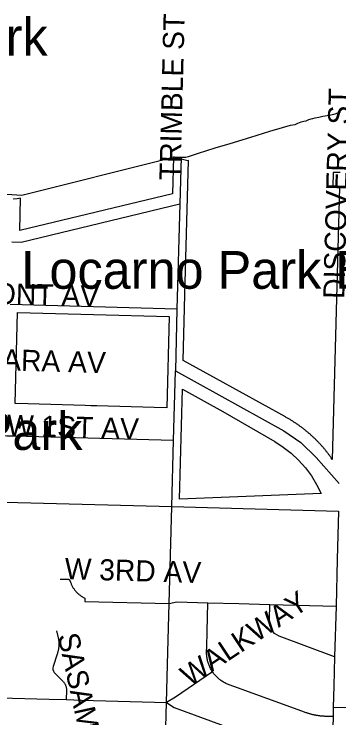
# Model space of a CAD drawing. Extents: x 482780 to 486928, y 5455974 to 5459836.
# Drawn here: x 484821 to 485252, y 5457356 to 5458288 of the extents above; entities that cross this region are included whole.
import ezdxf

# ---------------------------------------------------------------- set-up
doc = ezdxf.new("R2010")
doc.units = 0
for name, color, linetype in [('ParkLabels', 7, 'Continuous'), ('Parks', 7, 'Continuous'), ('StreetNames', 7, 'Continuous'), ('Streets', 7, 'Continuous')]:
    doc.layers.add(name, color=color, linetype=linetype)

msp = doc.modelspace()

# ---------------------------------------------------------------- linework, layer by layer
at = {"layer": 'Parks'}
for points in [[(484724.68, 5458054.79), (484831.03, 5458048.04), (485025.24, 5458096.46), (485029.94, 5458098.11), (485032.12, 5458098.56), (485033.54, 5458098.56), (485037.02, 5458098.36), (485048.62, 5458098.48), (485052.26, 5458098.98), (485057.52, 5458100.79), (485065.32, 5458103.77), (485087.63, 5458110.5), (485107.43, 5458116.47), (485134.69, 5458124.81), (485160.03, 5458132.57), (485176.84, 5458137.55), (485187.53, 5458140.47), (485190.31, 5458140.99), (485193.53, 5458141.57), (485197.17, 5458143.12), (485201.43, 5458145.07), (485204.99, 5458145.73), (485208.33, 5458146.37), (485211.87, 5458148.02), (485214.63, 5458149.17), (485217.22, 5458149.65), (485220.03, 5458150.17), (485225.09, 5458151.4), (485230.33, 5458152.67), (485233.27, 5458153.18), (485240.93, 5458154.27), (485246.55, 5458155.64), (485253.69, 5458158.37)], [(485253.08, 5458077.77), (485244.18, 5458078.02), (485243.68, 5458058.87), (485252.57, 5458058.62), (485242.83, 5457698.06), (485241.38, 5457700.11), (485240.79, 5457700.94), (485240.2, 5457701.76), (485239.61, 5457702.58), (485239.01, 5457703.39), (485238.4, 5457704.2), (485237.79, 5457705.01), (485237.18, 5457705.81), (485236.56, 5457706.62), (485235.94, 5457707.41), (485235.31, 5457708.21), (485234.68, 5457709), (485234.04, 5457709.79), (485233.4, 5457710.57), (485232.76, 5457711.35), (485232.11, 5457712.13), (485231.45, 5457712.9), (485230.79, 5457713.67), (485230.13, 5457714.43), (485229.46, 5457715.19), (485228.79, 5457715.95), (485228.12, 5457716.7), (485227.44, 5457717.45), (485226.75, 5457718.2), (485226.07, 5457718.94), (485225.37, 5457719.68), (485224.68, 5457720.42), (485223.98, 5457721.15), (485223.27, 5457721.87), (485222.56, 5457722.6), (485221.85, 5457723.31), (485221.13, 5457724.03), (485220.41, 5457724.74), (485219.69, 5457725.45), (485218.96, 5457726.15), (485218.23, 5457726.85), (485217.49, 5457727.54), (485216.75, 5457728.23), (485216, 5457728.92), (485215.26, 5457729.6), (485214.5, 5457730.28), (485213.75, 5457730.95), (485212.99, 5457731.62), (485212.23, 5457732.28), (485211.46, 5457732.94), (485210.69, 5457733.6), (485209.91, 5457734.25), (485209.13, 5457734.9), (485208.35, 5457735.54), (485207.57, 5457736.18), (485206.78, 5457736.81), (485205.99, 5457737.44), (485205.19, 5457738.07), (485204.39, 5457738.69), (485203.59, 5457739.3), (485202.78, 5457739.91), (485201.97, 5457740.52), (485201.16, 5457741.12), (485200.34, 5457741.72), (485199.52, 5457742.31), (485198.7, 5457742.9), (485197.87, 5457743.49), (485197.04, 5457744.07), (485196.21, 5457744.64), (485195.37, 5457745.21), (485194.53, 5457745.78), (485193.69, 5457746.34), (485192.84, 5457746.89), (485191.99, 5457747.44), (485191.14, 5457747.99), (485190.28, 5457748.53), (485189.42, 5457749.07), (485188.56, 5457749.6), (485187.7, 5457750.12), (485186.83, 5457750.65), (485185.96, 5457751.16), (485185.09, 5457751.67), (485184.21, 5457752.18), (485183.33, 5457752.68), (485182.45, 5457753.18), (485181.57, 5457753.67), (485180.68, 5457754.16), (485089.12, 5457804.57), (485045.17, 5457828.76), (485047.46, 5457915.91), (485052.13, 5458093.66), (485051.32, 5458093.59), (485032.11, 5458098.17), (485030.82, 5458049.81), (484828.42, 5458001.06), (484829.52, 5458043.76), (484824.88, 5458043.24), (484819.72, 5458042.76)]]:
    msp.add_lwpolyline(points, dxfattribs=at)
for points in [[(484825.52, 5457892.61), (484926.02, 5457889.93), (485026.52, 5457887.26), (485023.32, 5457766.41), (485006.62, 5457766.86), (484991.42, 5457767.27), (484976.17, 5457767.68), (484960.92, 5457768.1), (484945.72, 5457768.51), (484930.47, 5457768.92), (484922.82, 5457769.13), (484915.22, 5457769.34), (484899.97, 5457769.75), (484884.77, 5457770.16), (484869.52, 5457770.58), (484854.27, 5457770.99), (484839.02, 5457771.4), (484822.28, 5457771.85)], [(485166.63, 5457721.51), (485177.89, 5457714.27), (485188.44, 5457706.04), (485198.21, 5457696.88), (485207.11, 5457686.88), (485215.06, 5457676.11), (485222, 5457664.66), (485227.87, 5457652.63), (485040.27, 5457645.26), (485044.12, 5457791.06), (485097.88, 5457761.46)]]:
    msp.add_lwpolyline(points, close=True, dxfattribs=at)
at = {"layer": 'Streets'}
for points in [[(485042.26, 5458098.43), (485040.65, 5458036.5)], [(484818.03, 5457986.12), (484830.14, 5457985.8), (485040.65, 5458036.5), (485036.92, 5457897.06), (485034.78, 5457815.39), (485178.43, 5457735.86), (485200.98, 5457720.3), (485221.37, 5457700.44), (485252.11, 5457665.92)], [(485036.92, 5457897.06), (484815.82, 5457902.94)], [(485021.83, 5457326.75), (485023.18, 5457376.21), (485024.92, 5457442.66), (485026.61, 5457507.02), (485028.32, 5457571.26), (485030.02, 5457635.55), (485032.31, 5457722.91), (485034.78, 5457815.39)], [(485032.31, 5457722.91), (484821.19, 5457728.63), (484811.18, 5457728.59), (484590.21, 5457735.74)], [(483813.72, 5457599.7), (483930.19, 5457625.05), (483953.6, 5457629.93), (483977.08, 5457634.4), (484000.64, 5457638.46), (484024.27, 5457642.11), (484047.96, 5457645.35), (484071.7, 5457648.17), (484095.48, 5457650.57), (484119.3, 5457652.56), (484143.16, 5457654.14), (484167.04, 5457655.3), (484190.93, 5457656.04), (484214.84, 5457656.37), (484238.75, 5457656.27), (484262.65, 5457655.76), (484264.42, 5457655.71), (484364.4, 5457653.1), (484476.08, 5457650.28), (484587.88, 5457647.46), (484661.8, 5457645.45), (484808.97, 5457641.49), (485030.02, 5457635.55), (485251.12, 5457629.52)], [(485251.12, 5457629.52), (485249.39, 5457565.24), (485247.73, 5457503.43), (485245.91, 5457436.28), (485244.69, 5457397.85), (485244.13, 5457370.04), (485243.81, 5457357.35), (485242.35, 5457298)], [(484882.09, 5457539.54), (484893.45, 5457539.21), (484893.58, 5457539.07), (484893.7, 5457538.92), (484893.83, 5457538.78), (484893.95, 5457538.63), (484894.07, 5457538.48), (484894.18, 5457538.33), (484894.3, 5457538.17), (484894.41, 5457538.02), (484894.52, 5457537.86), (484894.62, 5457537.7), (484894.73, 5457537.53), (484894.83, 5457537.37), (484894.92, 5457537.2), (484895.02, 5457537.04), (484895.11, 5457536.87), (484895.2, 5457536.7), (484895.28, 5457536.53), (484895.36, 5457536.35), (484895.44, 5457536.18), (484895.52, 5457536), (484895.59, 5457535.82), (484895.66, 5457535.64), (484895.73, 5457535.46), (484895.78, 5457535.31), (484896.12, 5457534.37), (484896.46, 5457533.49), (484896.82, 5457532.62), (484897.2, 5457531.76), (484897.61, 5457530.92), (484898.04, 5457530.09), (484898.49, 5457529.26), (484898.95, 5457528.45), (484899.45, 5457527.65), (484899.96, 5457526.86), (484900.5, 5457526.09), (484901.05, 5457525.33), (484901.62, 5457524.59), (484902.21, 5457523.86), (484902.82, 5457523.16), (484903.45, 5457522.45), (484904.11, 5457521.78), (484904.77, 5457521.11), (484905.45, 5457520.47), (484906.15, 5457519.84), (484906.85, 5457519.25), (484907.59, 5457518.66), (484908.35, 5457518.08), (484909.11, 5457517.53), (484909.87, 5457517), (484910.67, 5457516.49), (484911.46, 5457516.01), (484912.27, 5457515.55), (484913.11, 5457515.1), (484913.95, 5457514.67), (484914.69, 5457514.32), (484914.62, 5457509.8), (485026.61, 5457507.02), (485036.75, 5457509.15), (485077.83, 5457508.05), (485118.96, 5457506.91), (485160.09, 5457505.83), (485247.73, 5457503.43)], [(485243.81, 5457357.35), (485233.77, 5457357.63), (485232.82, 5457357.66), (485231.91, 5457357.7), (485230.96, 5457357.76), (485230.01, 5457357.82), (485229.06, 5457357.9), (485228.11, 5457357.98), (485227.21, 5457358.07), (485226.3, 5457358.18), (485225.34, 5457358.3), (485224.4, 5457358.43), (485223.48, 5457358.57), (485222.55, 5457358.71), (485221.24, 5457358.94), (485220.7, 5457359.04), (485219.8, 5457359.22), (485218.89, 5457359.41), (485218.74, 5457359.45), (485217.93, 5457359.62), (485217.05, 5457359.82), (485216.12, 5457360.06), (485215.2, 5457360.29), (485214.33, 5457360.53), (485213.41, 5457360.78), (485212.52, 5457361.05), (485211.6, 5457361.33), (485210.7, 5457361.62), (485209.81, 5457361.91), (485208.94, 5457362.21), (485208.04, 5457362.53), (485202.6, 5457364.5), (485112.11, 5457397.26), (485106.14, 5457399.43), (485105.02, 5457399.85), (485103.88, 5457400.33), (485102.77, 5457400.82), (485101.65, 5457401.34), (485100.52, 5457401.92), (485099.45, 5457402.5), (485098.36, 5457403.13), (485097.31, 5457403.78), (485096.28, 5457404.46), (485095.26, 5457405.17), (485094.26, 5457405.9), (485093.28, 5457406.66), (485092.35, 5457407.44), (485092.07, 5457407.67), (485091.4, 5457408.25), (485090.47, 5457409.1), (485089.58, 5457409.97), (485088.75, 5457410.82), (485087.9, 5457411.72), (485087.05, 5457412.7), (485086.27, 5457413.64), (485085.5, 5457414.62), (485084.76, 5457415.62), (485084.07, 5457416.61), (485084.07, 5457416.61), (485083.38, 5457417.64), (485082.72, 5457418.71), (485082.1, 5457419.77), (485081.5, 5457420.85), (485080.93, 5457421.97), (485080.41, 5457423.04), (485079.88, 5457424.2), (485079.4, 5457425.37), (485078.97, 5457426.5), (485078.68, 5457427.28), (485078.55, 5457427.64), (485078.16, 5457428.84), (485077.8, 5457430.06), (485077.5, 5457431.24), (485077.21, 5457432.43), (485076.96, 5457433.64), (485076.73, 5457434.86), (485076.55, 5457436.11), (485076.4, 5457437.32), (485076.28, 5457438.56), (485076.19, 5457439.78), (485076.13, 5457441.04), (485076.12, 5457442.29), (485076.13, 5457443.46), (485076.3, 5457449.87), (485076.83, 5457469.97), (485077.83, 5457508.05)], [(485245.91, 5457436.28), (485172.16, 5457463.98), (485166.28, 5457467.31), (485162.44, 5457471.91), (485160.13, 5457477.8), (485159.62, 5457485.98), (485160.09, 5457505.83)], [(484877.24, 5457470.94), (484879.49, 5457461.53), (484879.67, 5457460.52), (484879.82, 5457459.57), (484879.95, 5457458.66), (484880.05, 5457457.71), (484880.14, 5457456.75), (484880.2, 5457455.81), (484880.25, 5457454.88), (484880.26, 5457453.94), (484880.26, 5457452.98), (484880.25, 5457452.03), (484880.21, 5457451.11), (484880.19, 5457450.82), (484880.14, 5457450.11), (484880.07, 5457449.19), (484879.97, 5457448.26), (484879.85, 5457447.31), (484879.7, 5457446.38), (484879.54, 5457445.43), (484879.36, 5457444.49), (484879.16, 5457443.58), (484878.94, 5457442.67), (484878.69, 5457441.75), (484878.42, 5457440.82), (484878.14, 5457439.91), (484872.84, 5457423.73), (484872.46, 5457422.09), (484872.46, 5457419.84), (484873, 5457417.65), (484874, 5457415.68), (484875.23, 5457414.22), (484885.54, 5457404.05), (484886.16, 5457403.4), (484886.71, 5457402.78), (484887.21, 5457402.14), (484887.69, 5457401.45), (484888.14, 5457400.73), (484888.55, 5457400.01), (484888.92, 5457399.26), (484889.26, 5457398.48), (484889.55, 5457397.71), (484889.8, 5457396.94), (484890.01, 5457396.13), (484890.17, 5457395.32), (484890.3, 5457394.48), (484890.38, 5457393.65), (484890.42, 5457392.83), (484890.42, 5457391.86), (484890.11, 5457379.8)], [(485084.07, 5457416.61), (485035.14, 5457383.22), (485023.18, 5457376.21)], [(484165.1, 5457395.05), (484186.03, 5457395.98), (484206.97, 5457396.54), (484227.91, 5457396.74), (484248.86, 5457396.57), (484257.49, 5457396.4), (484357.5, 5457393.72), (484581.07, 5457387.91), (484802.02, 5457382.22), (484867.32, 5457380.43), (484890.11, 5457379.8), (484910.5, 5457379.28), (485023.18, 5457376.21), (485033.05, 5457369.22), (485156.24, 5457324.57)], [(485244.13, 5457370.04), (485296.86, 5457368.53), (485345.46, 5457367.15)]]:
    msp.add_lwpolyline(points, dxfattribs=at)

# ---------------------------------------------------------------- texts
at = {"layer": 'ParkLabels'}
for s, p in [('Spanish Banks Beach Park', (484055.22, 5458232.68)), ('Locarno Park Beach', (484830.58, 5457923.96)), ('Westmount Park', (484417.39, 5457710.57))]:
    msp.add_text(s, height=50, dxfattribs=at).set_placement(p)
at = {"layer": 'StreetNames'}
for s, rotation, p in [('TRIMBLE ST', 88.51667, (485041.46, 5458067.47)), ('DISCOVERY ST', 88.454, (485258.7, 5457910.26)), ('BELMONT AV', 358.40012, (484691.98, 5457906.69)), ('LANGARA AV', 358.33122, (484702.99, 5457819.1)), ('W 1ST AV', 358.3375, (484811.26, 5457729.33)), ('W 3RD AV', 358.34446, (484887.77, 5457539.37)), ('WALKWAY', 33.5618, (485053.62, 5457396.41)), ('SASAMAT PLACE', 282.42485, (484878.59, 5457464.8))]:
    msp.add_text(s, height=28, rotation=rotation, dxfattribs=at).set_placement(p)

doc.saveas('drawing.dxf')
